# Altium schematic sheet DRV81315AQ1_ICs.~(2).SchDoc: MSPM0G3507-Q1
size 431 x 279 mm; Date: Not shown in title block; ApprovedBy: Not shown in title block; CheckedBy: Not shown in title block; Author: Not shown in title block; CompanyName: Not shown in title block; DrawnBy: Mojtaba Afshar; Engineer: Not shown in title block; Organization: Not shown in title block; Address1: Not shown in title block; Address2: Not shown in title block; Address3: Not shown in title block; Address4: Not shown in title block; DocumentNumber: 2; Revision: Use project parameter SCH_Rev; SheetNumber: 2; SheetTotal: 3; PageSetup: Record=PageOptions¦CenterHorizontal=True¦CenterVertical=True¦PrintScale=1.00¦XCorrection=1.00¦YCorrection=1.00¦PrintKind=0¦BorderSize=5000000¦LeftOffset=0¦BottomOffset=0¦Orientation=2¦PaperLength=1000¦PaperWidth=1000¦Scale=100¦PaperSource=15¦PrintQuality=600¦MediaType=1¦DitherType=10¦PaperKind=Letter¦PrintScaleMode=1
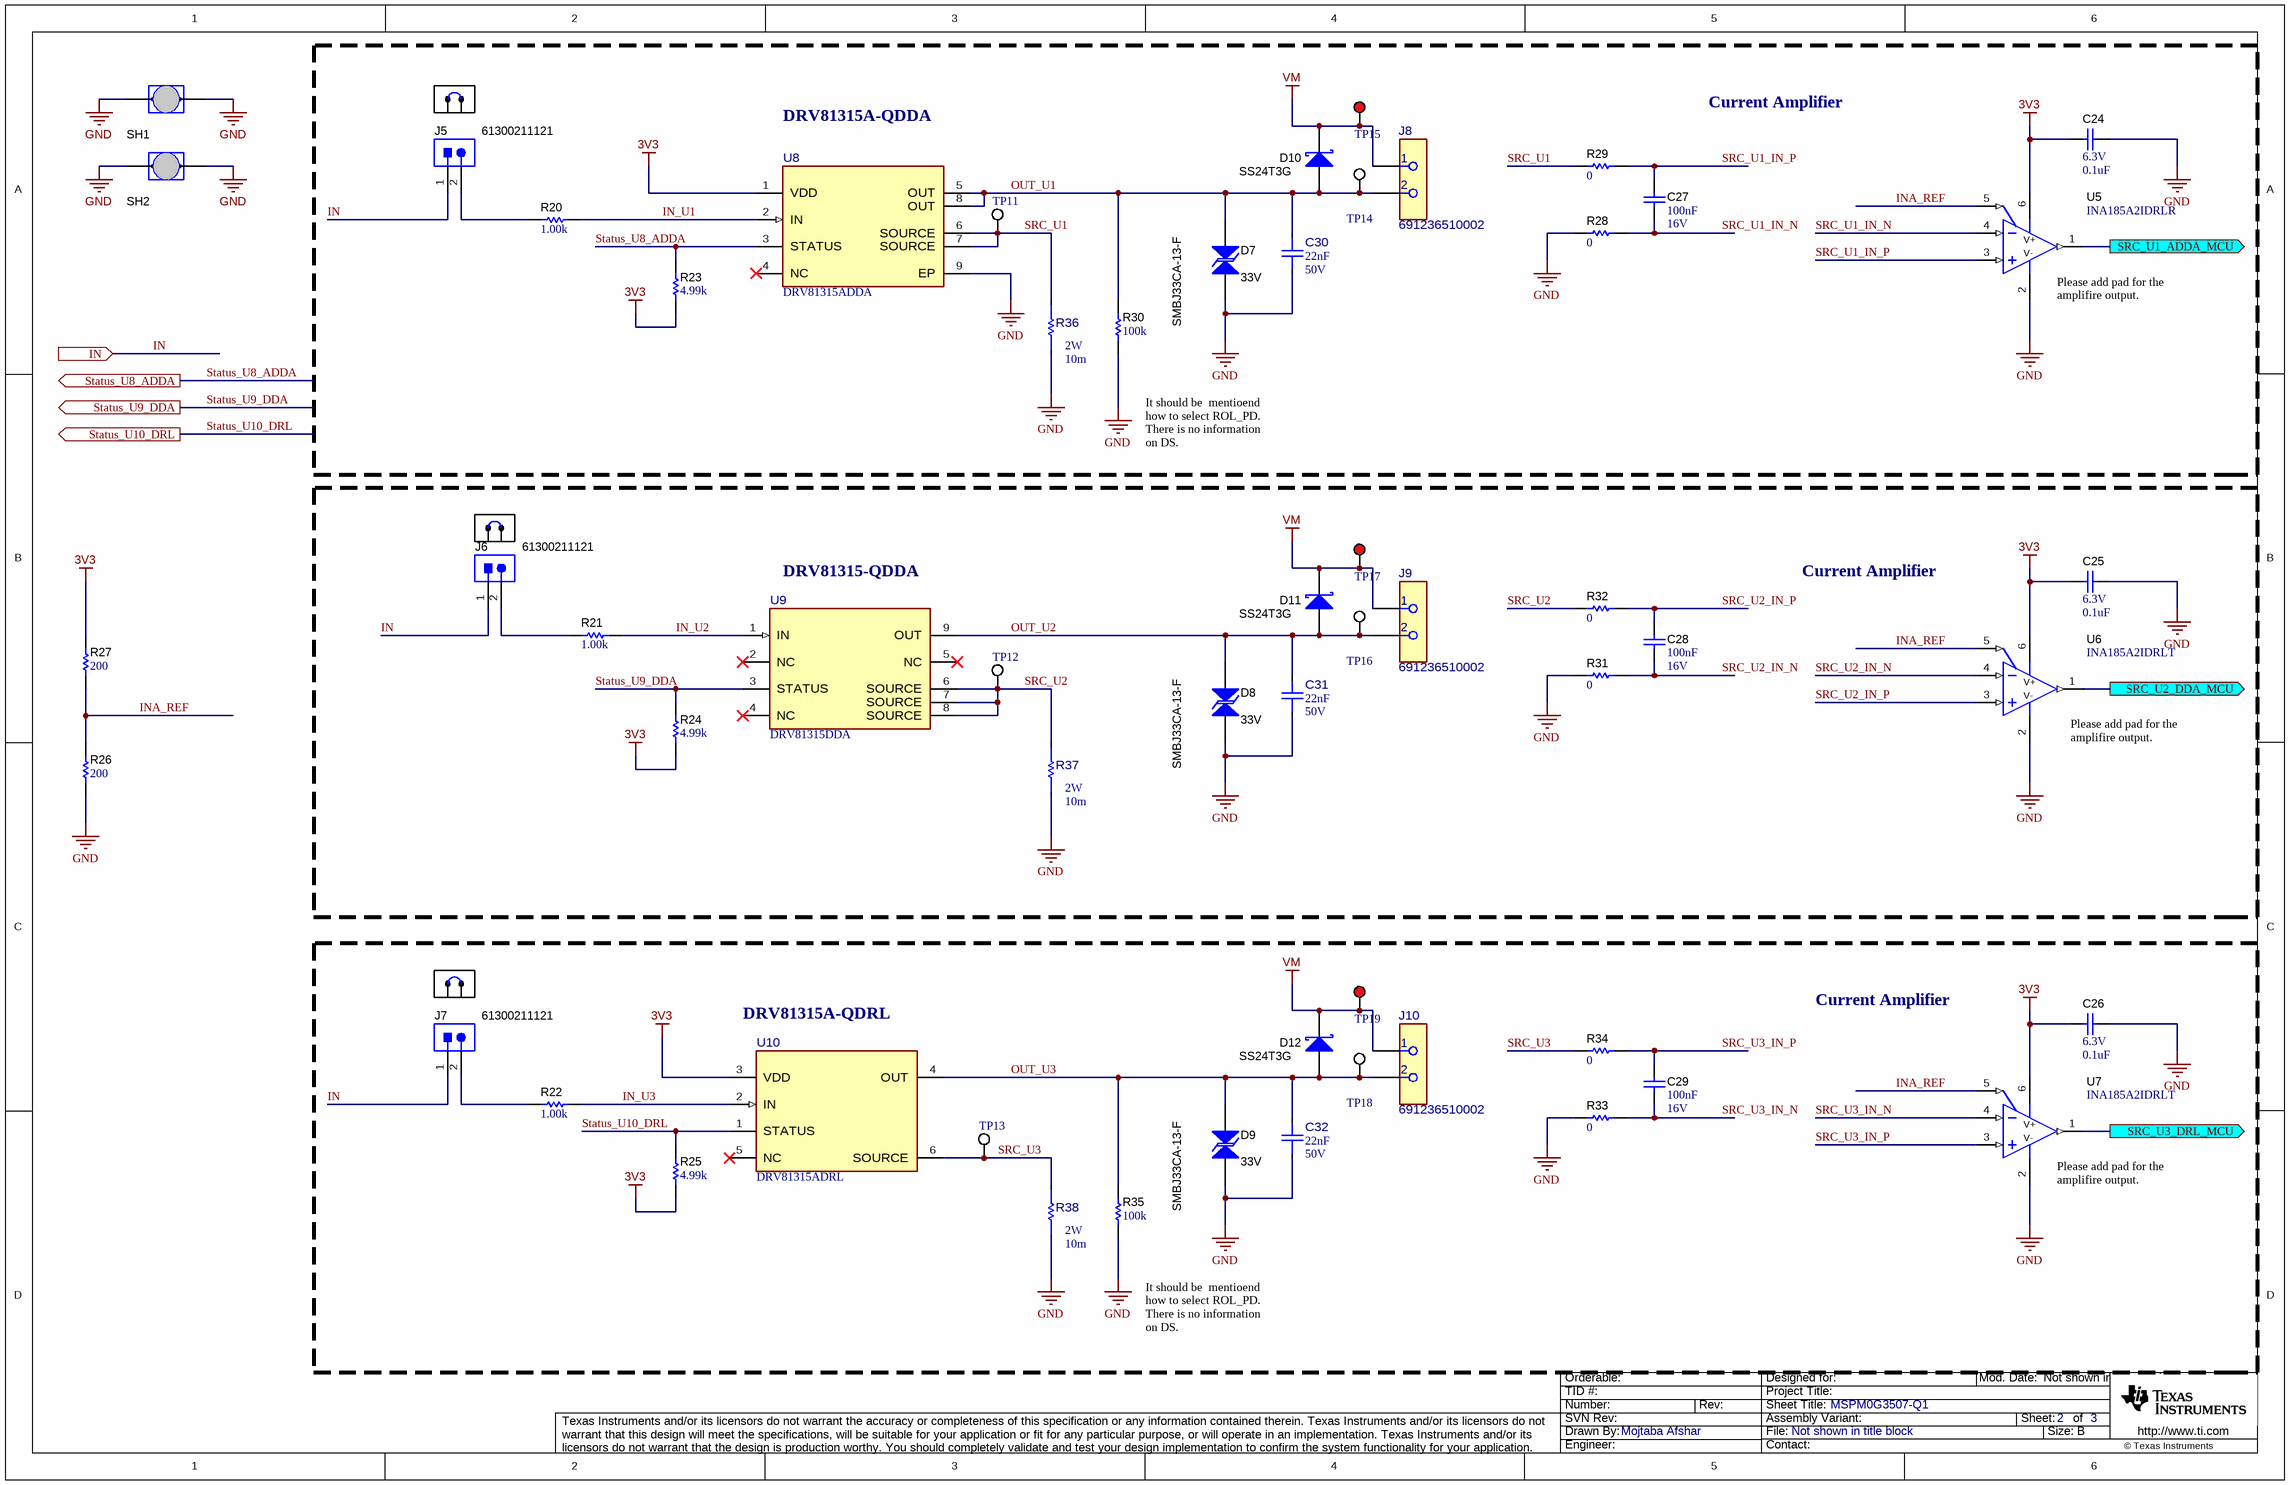
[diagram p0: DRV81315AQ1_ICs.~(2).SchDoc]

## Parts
C24  VDC_V: 6.3V  ValueDisplayed: 0.1uF  [0402]  (hidden comment: 885012105001)
C25  VDC_V: 6.3V  ValueDisplayed: 0.1uF  [0402]  (hidden comment: 885012105001)
C26  VDC_V: 6.3V  ValueDisplayed: 0.1uF  [0402]  (hidden comment: 885012105001)
C27  Cap_F: 100nF  VDC_V: 16V  [0603]  (hidden comment: 885012206046)
C28  Cap_F: 100nF  VDC_V: 16V  [0603]  (hidden comment: 885012206046)
C29  Cap_F: 100nF  VDC_V: 16V  [0603]  (hidden comment: 885012206046)
C30  Cap_F: 22nF  VDC_V: 50V  [FP-885012206091_0603-MFG]  (hidden comment: 885012206091)
C31  Cap_F: 22nF  VDC_V: 50V  [FP-885012206091_0603-MFG]  (hidden comment: 885012206091)
C32  Cap_F: 22nF  VDC_V: 50V  [FP-885012206091_0603-MFG]  (hidden comment: 885012206091)
D7  SMBJ33CA-13-F  value 33V  [SMB-Bi]
D8  SMBJ33CA-13-F  value 33V  [SMB-Bi]
D9  SMBJ33CA-13-F  value 33V  [SMB-Bi]
D10  SS24T3G  [SMB]
D11  SS24T3G  [SMB]
D12  SS24T3G  [SMB]
J5  61300211121  [WURTH_61300211121]
J6  61300211121  [WURTH_61300211121]
J7  61300211121  [WURTH_61300211121]
J8  691236510002  [FP-691236510002_HHR2-MFG]
J9  691236510002  [FP-691236510002_HHR2-MFG]
J10  691236510002  [FP-691236510002_HHR2-MFG]
R20  ValueDisplayed: 1.00k  [0603]  (hidden comment: RC0603FR-071KL)
R21  ValueDisplayed: 1.00k  [0603]  (hidden comment: RC0603FR-071KL)
R22  ValueDisplayed: 1.00k  [0603]  (hidden comment: RC0603FR-071KL)
R23  ValueDisplayed: 4.99k  [0603]  (hidden comment: RC0603FR-074K99L)
R24  ValueDisplayed: 4.99k  [0603]  (hidden comment: RC0603FR-074K99L)
R25  ValueDisplayed: 4.99k  [0603]  (hidden comment: RC0603FR-074K99L)
R26  ValueDisplayed: 200  [0603]  (hidden comment: RC0603FR-07200RL)
R27  ValueDisplayed: 200  [0603]  (hidden comment: RC0603FR-07200RL)
R28  ValueDisplayed: 0  [0603]  (hidden comment: ERJ-3GEY0R00V)
R29  ValueDisplayed: 0  [0603]  (hidden comment: ERJ-3GEY0R00V)
R30  ValueDisplayed: 100k  [0603]  (hidden comment: RC0603FR-07100KL)
R31  ValueDisplayed: 0  [0603]  (hidden comment: ERJ-3GEY0R00V)
R32  ValueDisplayed: 0  [0603]  (hidden comment: ERJ-3GEY0R00V)
R33  ValueDisplayed: 0  [0603]  (hidden comment: ERJ-3GEY0R00V)
R34  ValueDisplayed: 0  [0603]  (hidden comment: ERJ-3GEY0R00V)
R35  ValueDisplayed: 100k  [0603]  (hidden comment: RC0603FR-07100KL)
R36  Res_ohm: 10m  Power_W: 2W  [FP-PCS2512DR0100ET_2512-MFG]  (hidden comment: PCS2512DR0100ET)
R37  Res_ohm: 10m  Power_W: 2W  [FP-PCS2512DR0100ET_2512-MFG]  (hidden comment: PCS2512DR0100ET)
R38  Res_ohm: 10m  Power_W: 2W  [FP-PCS2512DR0100ET_2512-MFG]  (hidden comment: PCS2512DR0100ET)
SH1  Jumper_2p  [Harwin_D3082-05]  (value not drawn)
SH2  Jumper_2p  [Harwin_D3082-05]  (value not drawn)
SH-J5  60900213421  [Wurth_60900213421]  (value not drawn)
SH-J6  60900213421  [Wurth_60900213421]  (value not drawn)
SH-J7  60900213421  [Wurth_60900213421]  (value not drawn)
TP11  5002  [Keystone5002]  (value not drawn)
TP12  5002  [Keystone5002]  (value not drawn)
TP13  5002  [Keystone5002]  (value not drawn)
TP14  5012  [Keystone5012]  (value not drawn)
TP15  5010  [Keystone5010]  (value not drawn)
TP16  5012  [Keystone5012]  (value not drawn)
TP17  5010  [Keystone5010]  (value not drawn)
TP18  5012  [Keystone5012]  (value not drawn)
TP19  5010  [Keystone5010]  (value not drawn)
U5  INA185A2IDRLR  [DRL0006A]
U6  INA185A2IDRLT  [DRL0006A]
U7  INA185A2IDRLT  [DRL0006A]
U8  DRV81315ADDA  [DDA0008B-MFG]
U9  DRV81315DDA  [DDA0008B-MFG]
U10  DRV81315ADRL  [DRL0006A-MFG]

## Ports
IN (in), SRC_U1_ADDA_MCU (out), SRC_U2_DDA_MCU (out), SRC_U3_DRL_MCU (out), Status_U8_ADDA (out), Status_U9_DDA (out), Status_U10_DRL (out)

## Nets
3V3: C24.2 C25.2 C26.2 R23.1 R24.1 R25.1 R27.2 U5.6(V+) U6.6(V+) U7.6(V+) U8.1(VDD) U10.3(VDD)
GND: C24.1 C25.1 C26.1 C30.1 C31.1 C32.1 D7.1 D8.1 D9.1 R26.1 R28.1 R30.1 R31.1 R33.1 R35.1 R36.1 R37.1 R38.1 SH1.1 SH1.2 SH2.1 SH2.2 U5.2(V-) U6.2(V-) U7.2(V-) U8.9(EP)
VM: D10.1(K) D11.1(K) D12.1(K) J8.1 J9.1 J10.1 TP15.1 TP17.1 TP19.1
IN: J5.1 J6.1 J7.1 ; port IN
IN_U1: R20.2 U8.2(IN)
IN_U2: R21.2 U9.1(IN)
IN_U3: R22.2 U10.2(IN)
INA_REF: R26.2 R27.1 U5.5(REF) U6.5(REF) U7.5(REF)
OUT_U1: C30.2 D7.2 D10.2(A) J8.2 R30.2 TP14.1 U8.5(OUT) U8.8(OUT)
OUT_U2: C31.2 D8.2 D11.2(A) J9.2 TP16.1 U9.9(OUT)
OUT_U3: C32.2 D9.2 D12.2(A) J10.2 R35.2 TP18.1 U10.4(OUT)
SRC_U1: R29.1 R36.2 TP11.1 U8.6(SOURCE) U8.7(SOURCE)
SRC_U1_ADDA_MCU: U5.1(OUT) ; port SRC_U1_ADDA_MCU
SRC_U1_IN_N: C27.2 R28.2 U5.4(IN-)
SRC_U1_IN_P: C27.1 R29.2 U5.3(IN+)
SRC_U2: R32.1 R37.2 TP12.1 U9.6(SOURCE) U9.7(SOURCE) U9.8(SOURCE)
SRC_U2_DDA_MCU: U6.1(OUT) ; port SRC_U2_DDA_MCU
SRC_U2_IN_N: C28.2 R31.2 U6.4(IN-)
SRC_U2_IN_P: C28.1 R32.2 U6.3(IN+)
SRC_U3: R34.1 R38.2 TP13.1 U10.6(SOURCE)
SRC_U3_DRL_MCU: U7.1(OUT) ; port SRC_U3_DRL_MCU
SRC_U3_IN_N: C29.2 R33.2 U7.4(IN-)
SRC_U3_IN_P: C29.1 R34.2 U7.3(IN+)
Status_U8_ADDA: R23.2 U8.3(STATUS) ; port Status_U8_ADDA
Status_U9_DDA: R24.2 U9.3(STATUS) ; port Status_U9_DDA
Status_U10_DRL: R25.2 U10.1(STATUS) ; port Status_U10_DRL
NetJ5_2: J5.2 R20.1
NetJ6_2: J6.2 R21.1
NetJ7_2: J7.2 R22.1

Not connected (* = marked no-connect by the designer): U8 4(NC)*; U9 2(NC)* 4(NC)* 5(NC)*; U10 5(NC)*

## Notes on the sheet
- DRV81315A-QDDA
- Current Amplifier
- (near U5) Please add pad for the amplifire output.
- It should be  mentioend how to select ROL_PD. There is no information on DS.
- DRV81315-QDDA
- (near U6) Please add pad for the amplifire output.
- DRV81315A-QDRL
- (near U7) Please add pad for the amplifire output.

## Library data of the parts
C24-C26 = CMP-0006219-2: CAP, CERM, 0.1 uF, 6.3 V, +/- 20%, X5R, 0402; Manufacturer: Wurth Elektronik; TaMin_C: -55°C; Polarized: N; SizeAreaWB_mm2: 3; Value1: Unknown; U/M: EA; Value: 0.1uF; TaMax_C: 85°C; SizeZ_mm: 0.6; SizeX_mm: 1; SizeY_mm: 0.5; Cap_F: 100nF; AEC Category: Q200
C27-C29 = CMP-0006829-4: CAP, CERM, 0.1 uF, 16 V, +/- 10%, X7R, 0603; Manufacturer: Wurth Elektronik; TaMin_C: -55°C; Polarized: N; SizeAreaWB_mm2: 4.68; Value1: Unknown; U/M: EA; Value: 0.1uF; TaMax_C: 125°C; SizeZ_mm: 1; SizeX_mm: 1.6; SizeY_mm: 0.8; SizeArea_mm2: 1.28; AEC Category: Q200
C30-C32 = CMP-0120895-1: 0.022 µF ±10% 50V Ceramic Capacitor X7R 0603 (1608 Metric); Manufacturer: Wurth Electronics; AEC Qualified: No; SizeZ_mm: 0.87mm; TempCo: 15%; Value: 22nF
D7-D9 = CMP-0005564-3: Diode, TVS, Bi, 33 V, SMB; Manufacturer: Diodes Inc.; SizeX_mm: 5.6; Ppk: 600W; SizeAreaWB_mm2: 44.156; SizeZ_mm: 2.6; SizeArea_mm2: 21.336; SizeY_mm: 3.81; AEC Category: Q101
D10-D12 = CMP-0028778-2: Diode, Schottky, 40 V, 2 A, AEC-Q101, SMB; Manufacturer: ON Semiconductor; AEC Qualified: Y; Value: 40V; TJmax_C: 150°C; Value1: 2A; Green_Lifecycle: Active; Value2: 0.5V; SizeX_mm: 5.6; SizeAreaWB_mm2: 44.156; SizeY_mm: 3.81; SizeArea_mm2: 21.336; Green_REACh: Passed; SizeZ_mm: 2.6; AEC Category: Q101; Vf_V: 500mV
J5-J7 = CMP-0054794-2: Header, 2.54 mm, 2x1, Gold, TH; Manufacturer: Wurth Elektronik; Shrouded: N; Gender: Male; Green_REACh: Passed; Pitch_mm: 2.54; Green_Lifecycle: Active; Row_Count: 1; Cert_UL: Y
J8-J10 = CMP-0121282-1: 2 Position Wire to Board Terminal Block Horizontal with Board 0.200" (5.08mm) Through Hole; Manufacturer: Wurth Electronics; Current_A: 20A; Row_Count: 1; Voltage_V: 300V; AEC Qualified: No; Conn Gender: Female; Is Female: yes; Max Wire Gauge: 12; Min Wire Gauge: 30; SizeZ_mm: 18.1mm
R20-R22 = CMP-0022895-5: RES, 1.00 k, 1%, 0.1 W, 0603; Manufacturer: Yageo; Power_W: 100mW; TempCo: 100 ppm/C; Value_Code: 1k00; Value: 1.00k; EIA_Code: E96; Res_ohm: 1k; SizeX_mm: 1.6; SizeY_mm: 0.8; SizeZ_mm: 1; Value2: 0.1W; SizeArea_mm2: 1.28; AEC Qualified: N; VDC_V: 75V; AEC Category: Q200; SizeAreaWB_mm2: 4.68
R23-R25 = CMP-0023155-5: RES, 4.99 k, 1%, 0.1 W, 0603; Manufacturer: Yageo; Power_W: 100mW; TempCo: 100 ppm/C; Value_Code: 4k99; Value: 4.99k; EIA_Code: E96; SizeX_mm: 1.6; SizeY_mm: 0.8; SizeZ_mm: 1; Value2: 0.1W; SizeArea_mm2: 1.28; AEC Qualified: N; VDC_V: 75V; AEC Category: Q200; SizeAreaWB_mm2: 4.68
R26 R27 = CMP-0022902-5: RES, 200, 1%, 0.1 W, 0603; Manufacturer: Yageo; Power_W: 100mW; TempCo: 100 ppm/C; Value_Code: 200R; Value: 200; EIA_Code: E96; SizeX_mm: 1.6; SizeY_mm: 0.8; SizeZ_mm: 1; Value2: 0.1W; SizeArea_mm2: 1.28; AEC Qualified: N; VDC_V: 75V; AEC Category: Q200; SizeAreaWB_mm2: 4.68
R28 R29 R31-R34 = CMP-0025874-4: RES, 0, 5%, 0.1 W, AEC-Q200 Grade 0, 0603; Manufacturer: Panasonic; Power_W: 100mW; TempCo: 600 ppm/C; Value_Code: 0000; Value: 0; EIA_Code: E24; SizeX_mm: 1.6; SizeY_mm: 0.8; SizeZ_mm: 1; Value2: 0.1W; SizeArea_mm2: 1.28; AEC Qualified: Y; VDC_V: 50V; AEC Category: Q200; SizeAreaWB_mm2: 4.68
R30 R35 = CMP-0022735-5: RES, 100 k, 1%, 0.1 W, 0603; Manufacturer: Yageo; Power_W: 100mW; TempCo: 100 ppm/C; Value: 100k; EIA_Code: E96; SizeX_mm: 1.6; SizeY_mm: 0.8; SizeZ_mm: 1; Value2: 0.1W; SizeArea_mm2: 1.28; AEC Qualified: N; VDC_V: 75V; AEC Category: Q200; SizeAreaWB_mm2: 4.68
R36-R38 = CMP-0088493-1: 10 mOhms ±0.5% 2W Chip Resistor 2512 (6432 Metric) Automotive AEC-Q200, Current Sense, Moisture Resistant Metal Film; Manufacturer: Ohmite; SizeZ_mm: 0.664mm; AEC Grade: Grade 0; TempCo: 50ppm/°C; AEC Qualified: Yes; Tolerance_%: 0%
SH1 SH2 = CMP-0075110-1: 1mm Uninsulated Shorting Plug, 10.16mm spacing, TH; PartNumber: D3082-05; Manufacturer: Harwin; CNHeader: False; CompType: Jumper Wire; Green_Lifecycle: Active; Green_REACh: Passed
SH-J5-SH-J7 = CMP-0003761-2: Shunt, 2.54mm, Gold, Black; Manufacturer: Wurth Elektronik
TP11-TP13 = CMP-0055139-2: Test Point, Miniature, White, TH; Manufacturer: Keystone Electronics; ContactFinish: Silver; Green_REACh: Passed; CT: TRUE; Green_Lifecycle: Active; CNHeader: FALSE
TP14 TP16 TP18 = CMP-0055149-2: Test Point, Multipurpose, White, TH; Manufacturer: Keystone Electronics; ContactFinish: Silver; CT: TRUE; CNHeader: FALSE; Green_Lifecycle: Active; Green_REACh: Passed
TP15 TP17 TP19 = CMP-0055147-2: Test Point, Multipurpose, Red, TH; Manufacturer: Keystone Electronics; CT: TRUE; ContactFinish: Silver; Green_Lifecycle: Active; CNHeader: FALSE; Green_REACh: Passed
U5 = CMP-0085242-1: Bidirectional, Precision Low- and High-Side Voltage Output, Current-Sense Amplifier, DRL0006A (SOT-5X3-6); Alternate PartNumber: INA185A2IDRLT; Alternate Manufacturer: Texas Instruments; SizeY_mm: 1.6; SizeAreaWB_mm2: 6.76; AEC Category: Q200; SizeArea_mm2: 2.56; CompType: IC; AEC Qualified: N; SizeZ_mm: 0.6
U6 U7 = CMP-0085241-1: Bidirectional, Precision Low- and High-Side Voltage Output, Current-Sense Amplifier, DRL0006A (SOT-5X3-6); Alternate Manufacturer: Texas Instruments; Alternate PartNumber: INA185A2IDRLR; SizeZ_mm: 0.6; CompType: IC; SizeY_mm: 1.6; SizeAreaWB_mm2: 6.76; AEC Qualified: N; SizeArea_mm2: 2.56; AEC Category: Q200
U8 = CMP-0127675-1: Protected Low-Side Switch, HSOIC8; Manufacturer: Texas Instruments; SizeZ_mm: 1.7mm; AEC Qualified: Yes; AEC Grade: Grade 1; Max Supply Voltage: 5.5V; Min Supply Voltage: 3V; Nominal Supply Current: 40uA; Number Of Outputs: 1; Standoff Height: 0mm; TaMax_C: +125°C; TaMin_C: -40°C; TJmax_C: +150°C
U9 = CMP-0127704-1: Protected Low-Side Switch, HSOIC8; Manufacturer: Texas Instruments; SizeZ_mm: 1.7mm; AEC Qualified: Yes; AEC Grade: Grade 1; Max Supply Voltage: 5.5V; Min Supply Voltage: 3V; Nominal Supply Current: 40uA; Number Of Outputs: 1; Standoff Height: 0mm; TaMax_C: +125°C; TaMin_C: -40°C; TJmax_C: +150°C
U10 = CMP-0127676-1: Protected Low-Side Switch, SOT563; Manufacturer: Texas Instruments; SizeZ_mm: 0.6mm; AEC Qualified: Yes; AEC Grade: Grade 1; Max Supply Voltage: 5.5V; Min Supply Voltage: 3V; Nominal Supply Current: 40uA; Number Of Outputs: 1; Standoff Height: 0mm; TaMax_C: +125°C; TaMin_C: -40°C; TJmax_C: +150°C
